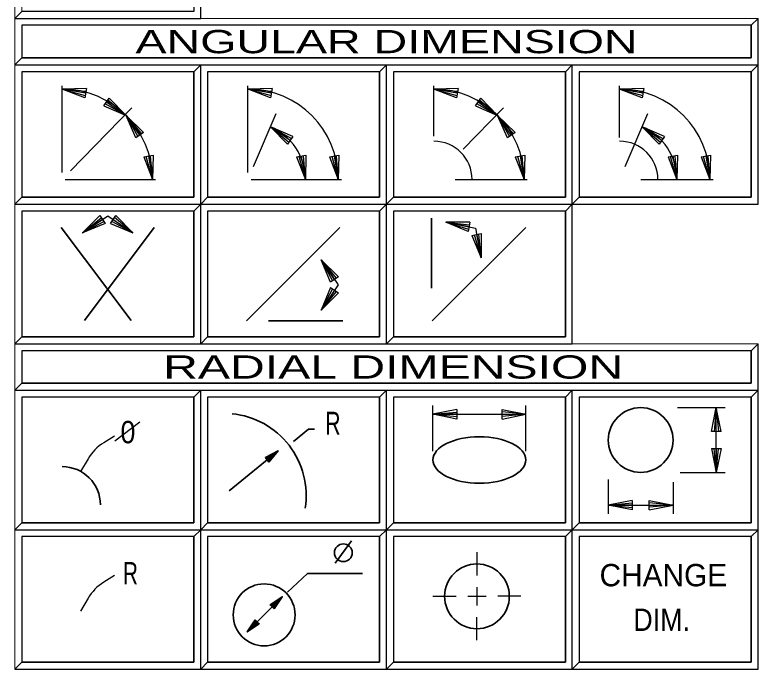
# Model space of a CAD drawing. Extents: x 95906.8 to 95923.6, y 90964.8 to 90972.8.
# Drawn here: x 95908.932 to 95910.532, y 90969.662 to 90971.069 of the extents above; entities that cross this region are included whole.
import ezdxf
from ezdxf.enums import TextEntityAlignment as Align

# ---------------------------------------------------------------- set-up
doc = ezdxf.new("R2010")
doc.units = 0
doc.header["$LTSCALE"] = 0.019
for name, color, linetype, lineweight in [('11', 7, 'Continuous', 25), ('12', 7, 'Continuous', 25), ('17', 7, 'Continuous', 25), ('2', 7, 'Continuous', 13), ('3', 7, 'Continuous', 25), ('50', 7, 'Continuous', 25), ('6', 7, 'Continuous', 25), ('7', 7, 'Continuous', 35)]:
    doc.layers.add(name, color=color, linetype=linetype, lineweight=lineweight)

msp = doc.modelspace()

# ---------------------------------------------------------------- linework, layer by layer
at = {"layer": '11'}
for points in [[(95909.3473, 90970.6767), (95909.7173, 90970.6767), (95909.7173, 90970.9467), (95909.3473, 90970.9467)], [(95909.7473, 90970.6767), (95910.1173, 90970.6767), (95910.1173, 90970.9467), (95909.7473, 90970.9467)], [(95910.1473, 90970.6767), (95910.5173, 90970.6767), (95910.5173, 90970.9467), (95910.1473, 90970.9467)], [(95908.9473, 90970.3767), (95909.3173, 90970.3767), (95909.3173, 90970.6467), (95908.9473, 90970.6467)], [(95909.3473, 90970.3767), (95909.7173, 90970.3767), (95909.7173, 90970.6467), (95909.3473, 90970.6467)], [(95909.7473, 90970.3767), (95910.1173, 90970.3767), (95910.1173, 90970.6467), (95909.7473, 90970.6467)], [(95909.3473, 90969.9767), (95909.7173, 90969.9767), (95909.7173, 90970.2467), (95909.3473, 90970.2467)], [(95909.7473, 90969.9767), (95910.1173, 90969.9767), (95910.1173, 90970.2467), (95909.7473, 90970.2467)], [(95910.1473, 90969.9767), (95910.5173, 90969.9767), (95910.5173, 90970.2467), (95910.1473, 90970.2467)], [(95910.1473, 90969.9767), (95910.5173, 90969.9767), (95910.5173, 90970.2467), (95910.1473, 90970.2467)], [(95908.9473, 90969.6767), (95909.3173, 90969.6767), (95909.3173, 90969.9467), (95908.9473, 90969.9467)], [(95909.3473, 90969.6767), (95909.7173, 90969.6767), (95909.7173, 90969.9467), (95909.3473, 90969.9467)], [(95909.7473, 90969.6767), (95910.1173, 90969.6767), (95910.1173, 90969.9467), (95909.7473, 90969.9467)], [(95910.1473, 90969.6767), (95910.5173, 90969.6767), (95910.5173, 90969.9467), (95910.1473, 90969.9467)]]:
    msp.add_lwpolyline(points, close=True, dxfattribs=at)
at = {"layer": '12'}
for points in [[(95908.9473, 90970.6767), (95909.3173, 90970.6767), (95909.3173, 90970.9467), (95908.9473, 90970.9467)], [(95908.9473, 90969.9767), (95909.3173, 90969.9767), (95909.3173, 90970.2467), (95908.9473, 90970.2467)]]:
    msp.add_lwpolyline(points, close=True, dxfattribs=at)
at = {"layer": '17'}
for points in [[(95908.9473, 90970.9767), (95910.5173, 90970.9767), (95910.5173, 90971.0467), (95908.9473, 90971.0467)], [(95908.9473, 90970.2767), (95910.5173, 90970.2767), (95910.5173, 90970.3467), (95908.9473, 90970.3467)]]:
    msp.add_lwpolyline(points, close=True, dxfattribs=at)
at = {"layer": '2'}
for points in [[(95908.9323, 90971.3617), (95908.9323, 90971.0617), (95908.9473, 90971.0767), (95908.9473, 90971.3467), (95909.3173, 90971.3467), (95909.3323, 90971.3617)], [(95908.9323, 90971.0617), (95908.9323, 90970.9617), (95908.9473, 90970.9767), (95908.9473, 90971.0467), (95910.5173, 90971.0467), (95910.5323, 90971.0617)], [(95908.9323, 90970.9617), (95908.9323, 90970.6617), (95908.9473, 90970.6767), (95908.9473, 90970.9467), (95909.3173, 90970.9467), (95909.3323, 90970.9617)], [(95909.3323, 90970.9617), (95909.3323, 90970.6617), (95909.3473, 90970.6767), (95909.3473, 90970.9467), (95909.7173, 90970.9467), (95909.7323, 90970.9617)], [(95909.7323, 90970.9617), (95909.7323, 90970.6617), (95909.7473, 90970.6767), (95909.7473, 90970.9467), (95910.1173, 90970.9467), (95910.1323, 90970.9617)], [(95910.1323, 90970.9617), (95910.1323, 90970.6617), (95910.1473, 90970.6767), (95910.1473, 90970.9467), (95910.5173, 90970.9467), (95910.5323, 90970.9617)], [(95908.9323, 90970.6617), (95908.9323, 90970.3617), (95908.9473, 90970.3767), (95908.9473, 90970.6467), (95909.3173, 90970.6467), (95909.3323, 90970.6617)], [(95909.3323, 90970.6617), (95909.3323, 90970.3617), (95909.3473, 90970.3767), (95909.3473, 90970.6467), (95909.7173, 90970.6467), (95909.7323, 90970.6617)], [(95909.7323, 90970.6617), (95909.7323, 90970.3617), (95909.7473, 90970.3767), (95909.7473, 90970.6467), (95910.1173, 90970.6467), (95910.1323, 90970.6617)], [(95908.9323, 90970.3617), (95908.9323, 90970.2617), (95908.9473, 90970.2767), (95908.9473, 90970.3467), (95910.5173, 90970.3467), (95910.5323, 90970.3617)], [(95908.9323, 90970.2617), (95908.9323, 90969.9617), (95908.9473, 90969.9767), (95908.9473, 90970.2467), (95909.3173, 90970.2467), (95909.3323, 90970.2617)], [(95909.3323, 90970.2617), (95909.3323, 90969.9617), (95909.3473, 90969.9767), (95909.3473, 90970.2467), (95909.7173, 90970.2467), (95909.7323, 90970.2617)], [(95909.7323, 90970.2617), (95909.7323, 90969.9617), (95909.7473, 90969.9767), (95909.7473, 90970.2467), (95910.1173, 90970.2467), (95910.1323, 90970.2617)], [(95910.1323, 90970.2617), (95910.1323, 90969.9617), (95910.1473, 90969.9767), (95910.1473, 90970.2467), (95910.5173, 90970.2467), (95910.5323, 90970.2617)], [(95910.1323, 90970.2617), (95910.1323, 90969.9617), (95910.1473, 90969.9767), (95910.1473, 90970.2467), (95910.5173, 90970.2467), (95910.5323, 90970.2617)], [(95908.9323, 90969.9617), (95908.9323, 90969.6617), (95908.9473, 90969.6767), (95908.9473, 90969.9467), (95909.3173, 90969.9467), (95909.3323, 90969.9617)], [(95909.3323, 90969.9617), (95909.3323, 90969.6617), (95909.3473, 90969.6767), (95909.3473, 90969.9467), (95909.7173, 90969.9467), (95909.7323, 90969.9617)], [(95909.7323, 90969.9617), (95909.7323, 90969.6617), (95909.7473, 90969.6767), (95909.7473, 90969.9467), (95910.1173, 90969.9467), (95910.1323, 90969.9617)], [(95910.1323, 90969.9617), (95910.1323, 90969.6617), (95910.1473, 90969.6767), (95910.1473, 90969.9467), (95910.5173, 90969.9467), (95910.5323, 90969.9617)]]:
    msp.add_lwpolyline(points, close=True, dxfattribs=at)
at = {"layer": '3'}
for points in [[(95908.9323, 90971.0617), (95909.3323, 90971.0617), (95909.3323, 90971.3617), (95909.3173, 90971.3467), (95909.3173, 90971.0767), (95908.9473, 90971.0767)], [(95908.9323, 90970.9617), (95910.5323, 90970.9617), (95910.5323, 90971.0617), (95910.5173, 90971.0467), (95910.5173, 90970.9767), (95908.9473, 90970.9767)], [(95908.9323, 90970.6617), (95909.3323, 90970.6617), (95909.3323, 90970.9617), (95909.3173, 90970.9467), (95909.3173, 90970.6767), (95908.9473, 90970.6767)], [(95909.3323, 90970.6617), (95909.7323, 90970.6617), (95909.7323, 90970.9617), (95909.7173, 90970.9467), (95909.7173, 90970.6767), (95909.3473, 90970.6767)], [(95909.7323, 90970.6617), (95910.1323, 90970.6617), (95910.1323, 90970.9617), (95910.1173, 90970.9467), (95910.1173, 90970.6767), (95909.7473, 90970.6767)], [(95910.1323, 90970.6617), (95910.5323, 90970.6617), (95910.5323, 90970.9617), (95910.5173, 90970.9467), (95910.5173, 90970.6767), (95910.1473, 90970.6767)], [(95908.9323, 90970.3617), (95909.3323, 90970.3617), (95909.3323, 90970.6617), (95909.3173, 90970.6467), (95909.3173, 90970.3767), (95908.9473, 90970.3767)], [(95909.3323, 90970.3617), (95909.7323, 90970.3617), (95909.7323, 90970.6617), (95909.7173, 90970.6467), (95909.7173, 90970.3767), (95909.3473, 90970.3767)], [(95909.7323, 90970.3617), (95910.1323, 90970.3617), (95910.1323, 90970.6617), (95910.1173, 90970.6467), (95910.1173, 90970.3767), (95909.7473, 90970.3767)], [(95908.9323, 90970.2617), (95910.5323, 90970.2617), (95910.5323, 90970.3617), (95910.5173, 90970.3467), (95910.5173, 90970.2767), (95908.9473, 90970.2767)], [(95908.9323, 90969.9617), (95909.3323, 90969.9617), (95909.3323, 90970.2617), (95909.3173, 90970.2467), (95909.3173, 90969.9767), (95908.9473, 90969.9767)], [(95909.3323, 90969.9617), (95909.7323, 90969.9617), (95909.7323, 90970.2617), (95909.7173, 90970.2467), (95909.7173, 90969.9767), (95909.3473, 90969.9767)], [(95909.7323, 90969.9617), (95910.1323, 90969.9617), (95910.1323, 90970.2617), (95910.1173, 90970.2467), (95910.1173, 90969.9767), (95909.7473, 90969.9767)], [(95910.1323, 90969.9617), (95910.5323, 90969.9617), (95910.5323, 90970.2617), (95910.5173, 90970.2467), (95910.5173, 90969.9767), (95910.1473, 90969.9767)], [(95910.1323, 90969.9617), (95910.5323, 90969.9617), (95910.5323, 90970.2617), (95910.5173, 90970.2467), (95910.5173, 90969.9767), (95910.1473, 90969.9767)], [(95908.9323, 90969.6617), (95909.3323, 90969.6617), (95909.3323, 90969.9617), (95909.3173, 90969.9467), (95909.3173, 90969.6767), (95908.9473, 90969.6767)], [(95909.3323, 90969.6617), (95909.7323, 90969.6617), (95909.7323, 90969.9617), (95909.7173, 90969.9467), (95909.7173, 90969.6767), (95909.3473, 90969.6767)], [(95909.7323, 90969.6617), (95910.1323, 90969.6617), (95910.1323, 90969.9617), (95910.1173, 90969.9467), (95910.1173, 90969.6767), (95909.7473, 90969.6767)], [(95910.1323, 90969.6617), (95910.5323, 90969.6617), (95910.5323, 90969.9617), (95910.5173, 90969.9467), (95910.5173, 90969.6767), (95910.1473, 90969.6767)]]:
    msp.add_lwpolyline(points, close=True, dxfattribs=at)
at = {"layer": '50'}
for p, q in [((95909.0341, 90970.7304), (95909.0341, 90970.9162)), ((95909.4341, 90970.7304), (95909.4341, 90970.9162)), ((95909.8341, 90970.8083), (95909.8341, 90970.9162)), ((95910.2341, 90970.8054), (95910.2341, 90970.9162)), ((95909.0523, 90970.7335), (95909.1842, 90970.8693)), ((95909.8975, 90970.7801), (95909.9842, 90970.8693)), ((95909.0409, 90970.7149), (95909.2353, 90970.7149)), ((95909.0798, 90970.7149), (95909.1643, 90970.7149)), ((95909.4409, 90970.7149), (95909.6353, 90970.7149)), ((95909.4798, 90970.7149), (95909.5643, 90970.7149)), ((95909.8798, 90970.7149), (95909.9643, 90970.7149)), ((95909.9284, 90970.7149), (95910.0353, 90970.7149)), ((95910.2798, 90970.7149), (95910.3643, 90970.7149)), ((95910.327, 90970.7149), (95910.4353, 90970.7149))]:
    msp.add_line(p, q, dxfattribs=at)
for centre, radius in [((95909.0342, 90970.715), 0.1944), ((95909.4342, 90970.715), 0.1944), ((95909.8342, 90970.715), 0.1944), ((95910.2342, 90970.715), 0.1944), ((95909.8342, 90970.715), 0.0823), ((95910.2342, 90970.715), 0.0823)]:
    msp.add_arc(centre, radius, 0, 90, dxfattribs=at)
at = {"layer": '6'}
for p, q in [((95909.0341, 90970.7304), (95909.0341, 90970.9162)), ((95909.4341, 90970.7304), (95909.4341, 90970.9162)), ((95909.8341, 90970.8083), (95909.8341, 90970.9162)), ((95910.2341, 90970.8054), (95910.2341, 90970.9162)), ((95909.0846, 90970.9005), (95909.0342, 90970.9094)), ((95909.0342, 90970.9094), (95909.0854, 90970.9052)), ((95909.4846, 90970.9005), (95909.4342, 90970.9094)), ((95909.4342, 90970.9094), (95909.4854, 90970.9052)), ((95909.8846, 90970.9005), (95909.8342, 90970.9094)), ((95909.8342, 90970.9094), (95909.8854, 90970.9052)), ((95910.2846, 90970.9005), (95910.2342, 90970.9094)), ((95910.2342, 90970.9094), (95910.2854, 90970.9052)), ((95909.1297, 90970.8819), (95909.1716, 90970.8525)), ((95909.9297, 90970.8819), (95909.9716, 90970.8525)), ((95909.0523, 90970.7335), (95909.1842, 90970.8693)), ((95909.1716, 90970.8525), (95909.1269, 90970.878)), ((95909.8975, 90970.7801), (95909.9842, 90970.8693)), ((95909.9716, 90970.8525), (95909.9269, 90970.878)), ((95909.201, 90970.8106), (95909.1716, 90970.8525)), ((95909.1716, 90970.8525), (95909.2049, 90970.8133)), ((95909.4462, 90970.7433), (95909.4949, 90970.8567)), ((95910.001, 90970.8106), (95909.9716, 90970.8525)), ((95909.9716, 90970.8525), (95910.0049, 90970.8133)), ((95910.2462, 90970.7433), (95910.2949, 90970.8567)), ((95909.5247, 90970.7991), (95909.4828, 90970.8285)), ((95909.4828, 90970.8285), (95909.5275, 90970.803)), ((95910.3247, 90970.7991), (95910.2828, 90970.8285)), ((95910.2828, 90970.8285), (95910.3275, 90970.803)), ((95909.2286, 90970.715), (95909.215, 90970.7646)), ((95909.2197, 90970.7654), (95909.2286, 90970.715)), ((95909.5576, 90970.715), (95909.544, 90970.7646)), ((95909.5487, 90970.7654), (95909.5576, 90970.715)), ((95909.6286, 90970.715), (95909.615, 90970.7646)), ((95909.6197, 90970.7654), (95909.6286, 90970.715)), ((95910.0286, 90970.715), (95910.015, 90970.7646)), ((95910.0197, 90970.7654), (95910.0286, 90970.715)), ((95910.3576, 90970.715), (95910.344, 90970.7646)), ((95910.3487, 90970.7654), (95910.3576, 90970.715)), ((95910.4286, 90970.715), (95910.415, 90970.7646)), ((95910.4197, 90970.7654), (95910.4286, 90970.715)), ((95909.0409, 90970.7149), (95909.2353, 90970.7149)), ((95909.0409, 90970.7149), (95909.2353, 90970.7149)), ((95909.0798, 90970.7149), (95909.1643, 90970.7149)), ((95909.4409, 90970.7149), (95909.6353, 90970.7149)), ((95909.4798, 90970.7149), (95909.5643, 90970.7149)), ((95909.8798, 90970.7149), (95909.9643, 90970.7149)), ((95909.9284, 90970.7149), (95910.0353, 90970.7149)), ((95910.2798, 90970.7149), (95910.3643, 90970.7149)), ((95910.327, 90970.7149), (95910.4353, 90970.7149)), ((95909.0781, 90970.6006), (95909.1181, 90970.6329)), ((95909.1207, 90970.629), (95909.0781, 90970.6006)), ((95909.1865, 90970.6006), (95909.1412, 90970.625)), ((95909.1439, 90970.629), (95909.1865, 90970.6006)), ((95909.4309, 90970.4109), (95909.6321, 90970.6121)), ((95909.8309, 90970.4109), (95910.0321, 90970.6121)), ((95909.91, 90970.6129), (95909.8598, 90970.623)), ((95909.8598, 90970.623), (95909.9109, 90970.6176)), ((95909.9364, 90970.5464), (95909.9217, 90970.5957)), ((95909.9263, 90970.5966), (95909.9364, 90970.5464)), ((95909.6202, 90970.4999), (95909.5918, 90970.5425)), ((95909.5918, 90970.5425), (95909.6241, 90970.5025)), ((95909.5918, 90970.4341), (95909.6162, 90970.4794)), ((95909.6202, 90970.4767), (95909.5918, 90970.4341)), ((95909.8323, 90970.1305), (95909.8323, 90970.2287)), ((95910.0323, 90970.1305), (95910.0323, 90970.2287)), ((95910.3587, 90970.2242), (95910.4611, 90970.2242)), ((95910.3587, 90970.2242), (95910.4611, 90970.2242)), ((95910.4423, 90970.0848), (95910.4423, 90970.2242)), ((95910.4423, 90970.173), (95910.4423, 90970.2242)), ((95910.4423, 90970.2242), (95910.4471, 90970.173)), ((95910.4423, 90970.0848), (95910.4423, 90970.2242)), ((95910.4423, 90970.173), (95910.4423, 90970.2242)), ((95910.4423, 90970.2242), (95910.4471, 90970.173)), ((95909.8323, 90970.2099), (95909.8835, 90970.2147)), ((95909.8323, 90970.2099), (95910.0323, 90970.2099)), ((95909.8835, 90970.2099), (95909.8323, 90970.2099)), ((95909.9811, 90970.2099), (95910.0323, 90970.2099)), ((95910.0323, 90970.2099), (95909.9811, 90970.2051)), ((95909.1472, 90970.1525), (95909.2015, 90970.1936)), ((95909.1471, 90970.1631), (95909.1237, 90970.1488)), ((95910.4423, 90970.0848), (95910.4375, 90970.136)), ((95910.4423, 90970.0848), (95910.4375, 90970.136)), ((95910.4423, 90970.136), (95910.4423, 90970.0848)), ((95910.4423, 90970.136), (95910.4423, 90970.0848)), ((95909.0898, 90970.1141), (95909.0736, 90970.0867)), ((95910.3644, 90970.0848), (95910.4611, 90970.0848)), ((95910.3644, 90970.0848), (95910.4611, 90970.0848)), ((95910.2097, 90970.0694), (95910.2097, 90969.9958)), ((95910.2097, 90970.0694), (95910.2097, 90969.9958)), ((95910.3491, 90970.0636), (95910.3491, 90969.9958)), ((95910.3491, 90970.0636), (95910.3491, 90969.9958)), ((95910.2097, 90970.0146), (95910.2609, 90970.0194)), ((95910.2097, 90970.0146), (95910.2609, 90970.0194)), ((95910.2097, 90970.0146), (95910.3491, 90970.0146)), ((95910.2609, 90970.0146), (95910.2097, 90970.0146)), ((95910.2097, 90970.0146), (95910.3491, 90970.0146)), ((95910.2609, 90970.0146), (95910.2097, 90970.0146)), ((95910.2979, 90970.0146), (95910.3491, 90970.0146)), ((95910.3491, 90970.0146), (95910.2979, 90970.0098)), ((95910.2979, 90970.0146), (95910.3491, 90970.0146)), ((95910.3491, 90970.0146), (95910.2979, 90970.0098)), ((95909.927, 90969.9131), (95909.927, 90969.8631)), ((95909.1471, 90969.8631), (95909.1237, 90969.8488)), ((95909.927, 90969.8381), (95909.927, 90969.7987)), ((95909.0898, 90969.8141), (95909.0736, 90969.7867)), ((95909.8323, 90969.8184), (95909.8823, 90969.8184)), ((95909.9073, 90969.8184), (95909.9467, 90969.8184)), ((95910.0217, 90969.8184), (95909.9717, 90969.8184)), ((95909.927, 90969.7237), (95909.927, 90969.7737))]:
    msp.add_line(p, q, dxfattribs=at)
at = {"layer": '6', "lineweight": 35}
for p, q in [((95909.8295, 90970.4815), (95909.8295, 90970.6315)), ((95909.1823, 90970.4117), (95909.0323, 90970.6117)), ((95909.0823, 90970.4117), (95909.2323, 90970.6117)), ((95909.4785, 90970.4109), (95909.6386, 90970.4109)), ((95909.3933, 90970.0455), (95909.4992, 90970.1312)), ((95909.4753, 90970.1119), (95909.4992, 90970.1312)), ((95909.4992, 90970.1312), (95909.4771, 90970.1097)), ((95909.6218, 90969.8893), (95909.6571, 90969.938)), ((95909.4324, 90969.7419), (95909.5079, 90969.8174)), ((95909.4862, 90969.7957), (95909.5079, 90969.8174)), ((95909.5079, 90969.8174), (95909.4882, 90969.7937)), ((95909.4324, 90969.7419), (95909.4521, 90969.7656)), ((95909.4541, 90969.7636), (95909.4324, 90969.7419))]:
    msp.add_line(p, q, dxfattribs=at)
at = {"layer": '6'}
for points in [[(95909.0864, 90970.9106), (95909.0828, 90970.8904), (95909.0342, 90970.9094)], [(95909.0864, 90970.9106), (95909.0342, 90970.9094), (95909.0838, 90970.8956)], [(95909.4864, 90970.9106), (95909.4828, 90970.8904), (95909.4342, 90970.9094)], [(95909.4864, 90970.9106), (95909.4342, 90970.9094), (95909.4838, 90970.8956)], [(95909.8864, 90970.9106), (95909.8828, 90970.8904), (95909.8342, 90970.9094)], [(95909.8864, 90970.9106), (95909.8342, 90970.9094), (95909.8838, 90970.8956)], [(95910.2864, 90970.9106), (95910.2828, 90970.8904), (95910.2342, 90970.9094)], [(95910.2864, 90970.9106), (95910.2342, 90970.9094), (95910.2838, 90970.8956)], [(95909.1238, 90970.8735), (95909.1355, 90970.8903), (95909.1716, 90970.8525)], [(95909.1238, 90970.8735), (95909.1716, 90970.8525), (95909.1325, 90970.886)], [(95909.9238, 90970.8735), (95909.9355, 90970.8903), (95909.9716, 90970.8525)], [(95909.9238, 90970.8735), (95909.9716, 90970.8525), (95909.9325, 90970.886)], [(95909.2094, 90970.8164), (95909.1926, 90970.8047), (95909.1716, 90970.8525)], [(95909.2094, 90970.8164), (95909.1716, 90970.8525), (95909.1969, 90970.8077)], [(95910.0094, 90970.8164), (95909.9926, 90970.8047), (95909.9716, 90970.8525)], [(95910.0094, 90970.8164), (95909.9716, 90970.8525), (95909.9969, 90970.8077)], [(95909.5306, 90970.8075), (95909.5189, 90970.7907), (95909.4828, 90970.8285)], [(95909.5306, 90970.8075), (95909.4828, 90970.8285), (95909.5219, 90970.795)], [(95910.3306, 90970.8075), (95910.3189, 90970.7907), (95910.2828, 90970.8285)], [(95910.3306, 90970.8075), (95910.2828, 90970.8285), (95910.3219, 90970.795)], [(95909.2096, 90970.7636), (95909.2298, 90970.7672), (95909.2286, 90970.715)], [(95909.2096, 90970.7636), (95909.2286, 90970.715), (95909.2246, 90970.7663)], [(95909.5386, 90970.7636), (95909.5588, 90970.7672), (95909.5576, 90970.715)], [(95909.5386, 90970.7636), (95909.5576, 90970.715), (95909.5536, 90970.7663)], [(95909.6096, 90970.7636), (95909.6298, 90970.7672), (95909.6286, 90970.715)], [(95909.6096, 90970.7636), (95909.6286, 90970.715), (95909.6246, 90970.7663)], [(95910.0096, 90970.7636), (95910.0298, 90970.7672), (95910.0286, 90970.715)], [(95910.0096, 90970.7636), (95910.0286, 90970.715), (95910.0246, 90970.7663)], [(95910.3386, 90970.7636), (95910.3588, 90970.7672), (95910.3576, 90970.715)], [(95910.3386, 90970.7636), (95910.3576, 90970.715), (95910.3536, 90970.7663)], [(95910.4096, 90970.7636), (95910.4298, 90970.7672), (95910.4286, 90970.715)], [(95910.4096, 90970.7636), (95910.4286, 90970.715), (95910.4246, 90970.7663)], [(95909.115, 90970.6375), (95909.1264, 90970.6205), (95909.0781, 90970.6006)], [(95909.115, 90970.6375), (95909.0781, 90970.6006), (95909.1235, 90970.6248)], [(95909.0781, 90970.6006), (95909.1323, 90970.6367), (95909.1865, 90970.6006)], [(95909.1382, 90970.6205), (95909.1496, 90970.6375), (95909.1865, 90970.6006)], [(95909.1382, 90970.6205), (95909.1865, 90970.6006), (95909.1467, 90970.6332)], [(95909.8598, 90970.623), (95909.9236, 90970.6102), (95909.9364, 90970.5464)], [(95909.912, 90970.623), (95909.908, 90970.6029), (95909.8598, 90970.623)], [(95909.912, 90970.623), (95909.8598, 90970.623), (95909.909, 90970.608)], [(95909.9163, 90970.5946), (95909.9364, 90970.5986), (95909.9364, 90970.5464)], [(95909.9163, 90970.5946), (95909.9364, 90970.5464), (95909.9312, 90970.5976)], [(95909.5918, 90970.5425), (95909.6279, 90970.4883), (95909.5918, 90970.4341)], [(95909.6287, 90970.5056), (95909.6117, 90970.4942), (95909.5918, 90970.5425)], [(95909.6287, 90970.5056), (95909.5918, 90970.5425), (95909.616, 90970.4971)], [(95909.6117, 90970.4824), (95909.6287, 90970.471), (95909.5918, 90970.4341)], [(95909.6117, 90970.4824), (95909.5918, 90970.4341), (95909.6244, 90970.4739)], [(95910.4525, 90970.173), (95910.4321, 90970.173), (95910.4423, 90970.2242)], [(95910.4525, 90970.173), (95910.4321, 90970.173), (95910.4423, 90970.2242)], [(95910.4525, 90970.173), (95910.4423, 90970.2242), (95910.4373, 90970.173)], [(95910.4525, 90970.173), (95910.4423, 90970.2242), (95910.4373, 90970.173)], [(95909.8835, 90970.2201), (95909.8835, 90970.1997), (95909.8323, 90970.2099)], [(95909.8835, 90970.2201), (95909.8323, 90970.2099), (95909.8835, 90970.2049)], [(95909.9811, 90970.1997), (95909.9811, 90970.2201), (95910.0323, 90970.2099)], [(95909.9811, 90970.1997), (95910.0323, 90970.2099), (95909.9811, 90970.2149)], [(95910.4321, 90970.136), (95910.4525, 90970.136), (95910.4423, 90970.0848)], [(95910.4321, 90970.136), (95910.4423, 90970.0848), (95910.4473, 90970.136)], [(95910.4321, 90970.136), (95910.4525, 90970.136), (95910.4423, 90970.0848)], [(95910.4321, 90970.136), (95910.4423, 90970.0848), (95910.4473, 90970.136)], [(95910.2609, 90970.0248), (95910.2609, 90970.0044), (95910.2097, 90970.0146)], [(95910.2609, 90970.0248), (95910.2097, 90970.0146), (95910.2609, 90970.0096)], [(95910.2609, 90970.0248), (95910.2609, 90970.0044), (95910.2097, 90970.0146)], [(95910.2609, 90970.0248), (95910.2097, 90970.0146), (95910.2609, 90970.0096)], [(95910.2979, 90970.0044), (95910.2979, 90970.0248), (95910.3491, 90970.0146)], [(95910.2979, 90970.0044), (95910.2979, 90970.0248), (95910.3491, 90970.0146)], [(95910.2979, 90970.0044), (95910.3491, 90970.0146), (95910.2979, 90970.0196)], [(95910.2979, 90970.0044), (95910.3491, 90970.0146), (95910.2979, 90970.0196)]]:
    msp.add_lwpolyline(points, dxfattribs=at)
at = {"layer": '6', "lineweight": 35}
for points in [[(95909.5319, 90970.1513), (95909.5647, 90970.1782), (95909.5773, 90970.1782)], [(95909.4792, 90970.1071), (95909.4715, 90970.1167), (95909.4992, 90970.1312)], [(95909.4792, 90970.1071), (95909.4992, 90970.1312), (95909.4734, 90970.1142)], [(95909.5193, 90969.8271), (95909.5621, 90969.8674), (95909.6806, 90969.8674)], [(95909.4905, 90969.7913), (95909.4818, 90969.8), (95909.5079, 90969.8174)], [(95909.4905, 90969.7913), (95909.5079, 90969.8174), (95909.4841, 90969.7978)], [(95909.4498, 90969.768), (95909.4585, 90969.7593), (95909.4324, 90969.7419)], [(95909.4498, 90969.768), (95909.4324, 90969.7419), (95909.4562, 90969.7615)]]:
    msp.add_lwpolyline(points, dxfattribs=at)
for centre, radius in [((95910.2794, 90970.1545), 0.0697), ((95910.2794, 90970.1545), 0.0697), ((95909.6394, 90969.912), 0.0191), ((95909.927, 90969.8184), 0.0697), ((95909.4689, 90969.7784), 0.0666)]:
    msp.add_circle(centre, radius, dxfattribs=at)
at = {"layer": '6'}
for centre, radius, start, end in [((95909.0342, 90970.715), 0.1944, 0, 90), ((95909.4342, 90970.715), 0.1944, 0, 90), ((95909.8342, 90970.715), 0.1944, 0, 90), ((95910.2342, 90970.715), 0.1944, 0, 90), ((95909.4342, 90970.715), 0.1234, 0, 66.8084), ((95910.2342, 90970.715), 0.1234, 0, 66.8084), ((95909.8342, 90970.715), 0.0823, 0, 90), ((95910.2342, 90970.715), 0.0823, 0, 90), ((95909.1763, 90970.0638), 0.1, 121.7335, 149.804), ((95909.1763, 90969.7638), 0.1, 121.7335, 149.804)]:
    msp.add_arc(centre, radius, start, end, dxfattribs=at)
at = {"layer": '6', "lineweight": 35}
for centre, radius, start, end in [((95909.3829, 90970.0354), 0.1764, 350.954, 84.4361), ((95909.0342, 90970.015), 0.0823, 0, 90)]:
    msp.add_arc(centre, radius, start, end, dxfattribs=at)
msp.add_ellipse((95909.9323, 90970.1117), major_axis=(-0.1, 0), ratio=0.5, dxfattribs=at)

# ---------------------------------------------------------------- texts
at = {"layer": '6'}
for s, height, width, p in [('R', 0.0491, 0.7, (95909.6168, 90970.1662)), ('0', 0.048, 0.9, (95909.1757, 90970.1476)), ('R', 0.048, 0.7, (95909.181, 90969.844)), ('DIM.', 0.048, 0.9, (95910.3246, 90969.7439))]:
    msp.add_text(s, height=height, dxfattribs=dict(at, width=width)).set_placement(p, align=Align.CENTER)
msp.add_text('CHANGE', height=0.048, dxfattribs=at).set_placement((95910.3283, 90969.8399), align=Align.CENTER)
at = {"layer": '7'}
for s, width, p in [('   ANGULAR DIMENSION   ', 1.5, (95909.7323, 90970.9867)), ('    RADIAL DIMENSION   ', 1.55, (95909.7322, 90970.2867))]:
    msp.add_text(s, height=0.04999, dxfattribs=dict(at, width=width)).set_placement(p, align=Align.CENTER)

doc.saveas('drawing.dxf')
